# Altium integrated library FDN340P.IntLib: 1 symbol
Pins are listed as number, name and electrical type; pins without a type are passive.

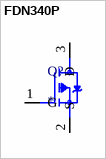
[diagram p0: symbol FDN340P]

## FDN340P
designator Q?
FDN340P Series 20V 70 mOhm Single P-Ch Logic Level PowerTrench Mosfet SSOT-3
footprint SOT95P240X120-3N
pins: 1 G, 2 S, 3 D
